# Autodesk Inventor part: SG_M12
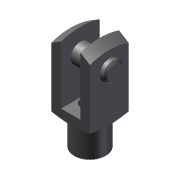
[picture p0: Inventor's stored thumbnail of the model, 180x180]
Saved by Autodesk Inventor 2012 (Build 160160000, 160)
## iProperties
Company: CAD-Verlag
Created: 2004-09
Part Number: SG_M12
Document SubType Name: Modeling
Designer: Greiling
Manufacturer: Standard
Standards Organization: Custom
Density: 1 g/cm^3
Checked By: Jürgen Kronas
Stock Number: 10-10021
Material: Standard
Übersetzungsnorm: STEP AP203
Dateiname: s:/PartAssembly/iodir/wkb1973860_no0//0//6145_SG_M12x1_25.stp
Postprozessor: Build: 096e, Release: 9 RTM - Date: Thu 06/17/2004
Gesendete Einheiten: MILLIMETERS
Unbestimmtheit: 1.0000000000000002e-06
Author: Juergen Kronas
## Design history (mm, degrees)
feature "Basis1"
node "Volumenkörper1"
node "Volumenkörpern"
node "Oberflächenkörpern"
